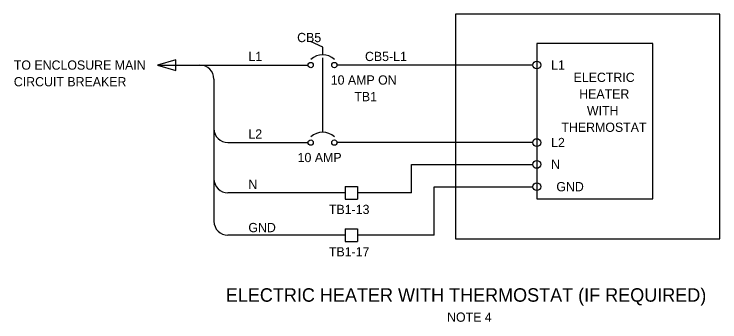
# Model space of a CAD drawing. Extents: x -0.472 to 0.292, y 0.05 to 0.383.
import ezdxf

# ---------------------------------------------------------------- set-up
doc = ezdxf.new("R2010")
doc.units = 0
for name, color, linetype in [('Default', 7, 'Continuous'), ('HS_Dimensions_and_Text', 7, 'Continuous'), ('HS_Electrical_Cable', 7, 'Continuous'), ('Sheets_General Details - Sheet Number Text', 7, 'Continuous'), ('Sheets_General Details - Total Sheet Number Text', 7, 'Continuous')]:
    doc.layers.add(name, color=color, linetype=linetype)

# ---------------------------------------------------------------- blocks, each defined once
blk = doc.blocks.new('ARROW')
at = {"layer": 'Default'}
blk.add_lwpolyline([(0, 0), (-0.00556, 0.00159), (-0.00556, -0.00159)], close=True, dxfattribs=at)

msp = doc.modelspace()

# ---------------------------------------------------------------- linework, layer by layer
at = {"layer": 'HS_Dimensions_and_Text'}
msp.add_lwpolyline([(0.00555, 0.13929), (0.29177, 0.13929), (0.29177, 0.38252), (0.00555, 0.38252)], close=True, dxfattribs=at)
at = {"layer": 'HS_Electrical_Cable'}
for p, q in [((-0.31683, 0.32739), (-0.17671, 0.32739)), ((-0.17671, 0.32739), (-0.15395, 0.32739)), ((0.0894, 0.32739), (-0.12268, 0.32739)), ((-0.25586, 0.31222), (-0.25586, 0.15846)), ((-0.24069, 0.24352), (-0.15395, 0.24352)), ((0.0894, 0.24352), (-0.12268, 0.24352)), ((-0.04195, 0.18916), (-0.04195, 0.21991)), ((-0.04195, 0.21991), (0.0894, 0.21991)), ((-0.01759, 0.1433), (-0.01759, 0.19576)), ((-0.01759, 0.19576), (0.0894, 0.19576)), ((-0.11394, 0.18916), (-0.24069, 0.18916)), ((-0.04195, 0.18916), (-0.10029, 0.18916)), ((-0.11394, 0.1433), (-0.24069, 0.1433)), ((-0.01759, 0.1433), (-0.10029, 0.1433))]:
    msp.add_line(p, q, dxfattribs=at)
for centre, start, end in [((-0.27103, 0.31222), 360, 90), ((-0.24069, 0.25869), 180, 270), ((-0.24069, 0.20433), 180, 270), ((-0.24069, 0.15846), 180, 270)]:
    msp.add_arc(centre, 0.01517, start, end, dxfattribs=at)
at = {"layer": 'Sheets_General Details - Sheet Number Text'}
msp.add_lwpolyline([(0.09362, 0.18259), (0.2192, 0.18259), (0.2192, 0.35066), (0.09362, 0.35066)], close=True, dxfattribs=at)
at = {"layer": 'Sheets_General Details - Total Sheet Number Text'}
for p, q in [((-0.1381, 0.34668), (-0.15131, 0.35277)), ((-0.1381, 0.33856), (-0.1381, 0.34668)), ((-0.1381, 0.2547), (-0.1381, 0.33513)), ((-0.11394, 0.19599), (-0.10029, 0.19599)), ((-0.11394, 0.19599), (-0.11394, 0.18234)), ((-0.10029, 0.19599), (-0.10029, 0.18234)), ((-0.11394, 0.18234), (-0.10029, 0.18234)), ((-0.11394, 0.15012), (-0.10029, 0.15012)), ((-0.11394, 0.15012), (-0.11394, 0.13647)), ((-0.10029, 0.15012), (-0.10029, 0.13647)), ((-0.11394, 0.13647), (-0.10029, 0.13647))]:
    msp.add_line(p, q, dxfattribs=at)
for centre, radius in [((-0.15111, 0.32739), 0.00284), ((-0.12552, 0.32739), 0.00284), ((0.09362, 0.32739), 0.00422), ((-0.15111, 0.24352), 0.00284), ((-0.12552, 0.24352), 0.00284), ((0.09362, 0.24352), 0.00422), ((0.09362, 0.21991), 0.00422), ((0.09362, 0.19576), 0.00422)]:
    msp.add_circle(centre, radius, dxfattribs=at)
for centre in [(-0.1381, 0.32017), (-0.1381, 0.2363)]:
    msp.add_arc(centre, 0.0184, 46.35835, 133.64165, dxfattribs=at)

# ---------------------------------------------------------------- block references
at = {"layer": 'HS_Electrical_Cable', "xscale": 3.5827662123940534, "yscale": 3.582766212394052, "rotation": 179.99999999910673}
msp.add_blockref('ARROW', (-0.31683, 0.32739), dxfattribs=at)

# ---------------------------------------------------------------- texts
at = {"layer": 'HS_Dimensions_and_Text'}
for s, p in [('CB5', (-0.16578, 0.3522)), ('L1', (-0.21856, 0.33173)), ('CB5-L1', (-0.09234, 0.33173)), ('TO ENCLOSURE MAIN ', (-0.47242, 0.32239)), ('L1', (0.1091, 0.32246)), ('CIRCUIT BREAKER', (-0.47242, 0.30439)), ('10 AMP ON ', (-0.12941, 0.30624)), ('ELECTRIC', (0.13345, 0.30913)), ('TB1', (-0.10388, 0.28824)), ('HEATER', (0.1395, 0.29113)), ('WITH ', (0.14788, 0.27313)), ('THERMOSTAT', (0.12024, 0.25513)), ('L2', (-0.21856, 0.24786)), ('L2', (0.1091, 0.2386)), ('10 AMP', (-0.16525, 0.22237)), ('N', (0.1091, 0.21499)), ('N', (-0.21856, 0.19331)), ('GND', (0.11477, 0.19083)), ('TB1-13', (-0.13137, 0.1662)), ('GND', (-0.21856, 0.14658)), ('TB1-17', (-0.13137, 0.12034))]:
    msp.add_text(s, height=0.01, rotation=360, dxfattribs=at).set_placement(p)
for s, height, p in [('ELECTRIC HEATER WITH THERMOSTAT (IF REQUIRED)', 0.0145833, (-0.24299, 0.07133)), ('NOTE 4', 0.01, (-0.00348, 0.04967))]:
    msp.add_text(s, height=height, dxfattribs=at).set_placement(p)

doc.saveas('drawing.dxf')
